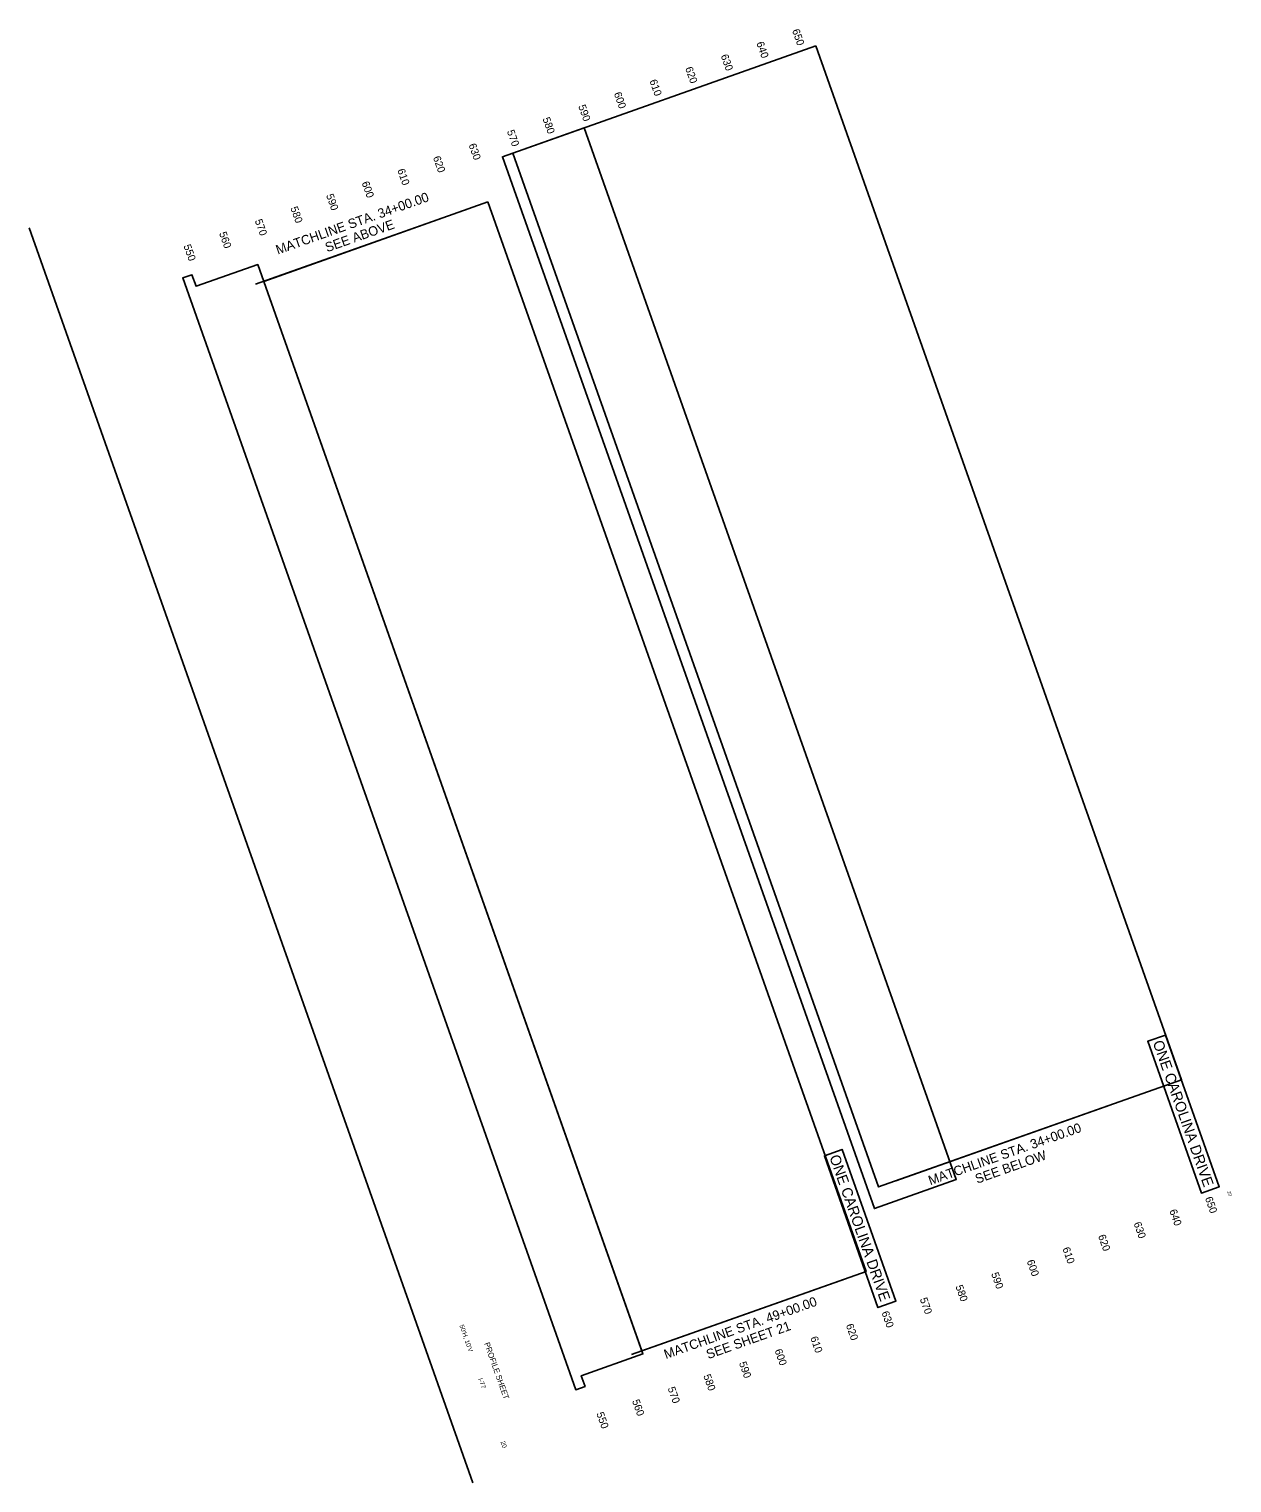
# Model space of a CAD drawing. Extents: x 1995206 to 1996796, y 1127223 to 1129145.
import ezdxf

# ---------------------------------------------------------------- set-up
doc = ezdxf.new("R2010")
doc.units = 0
for name, color, linetype in [('RD_DDB_ElevTX', 7, 'Continuous'), ('RD_SHT_MatchLine', 7, 'Continuous'), ('RD_SHT_ShtClip', 7, 'Continuous'), ('RD_SHT_TX', 7, 'Continuous')]:
    doc.layers.add(name, color=color, linetype=linetype)

msp = doc.modelspace()

# ---------------------------------------------------------------- linework, layer by layer
at = {"layer": 'RD_SHT_MatchLine'}
for p, q in [((1995787.8, 1128907.4), (1995505, 1128807.4)), ((1996634.9, 1127722.1), (1996352.1, 1127622)), ((1996285.2, 1127492.3), (1996002.3, 1127392.2))]:
    msp.add_line(p, q, dxfattribs=at)
at = {"layer": 'RD_SHT_ShtClip'}
for points in [[(1996246.1, 1129122.6), (1996729.6, 1127755.6), (1996329, 1127613.9), (1995845.4, 1128980.8)], [(1995939.8, 1129014.3), (1996431.8, 1127623.7), (1996323.5, 1127585.4), (1995831.6, 1128976)], [(1995812.2, 1128916.1), (1996312.5, 1127502), (1996016.1, 1127397.1), (1995515.8, 1128811.2)], [(1995515.8, 1128811.2), (1996017.5, 1127393.2), (1995935.9, 1127364.3), (1995940.9, 1127350.2), (1995928.6, 1127345.9), (1995408.7, 1128815.7), (1995421, 1128820), (1995426.4, 1128804.6), (1995508, 1128833.4)]]:
    msp.add_lwpolyline(points, close=True, dxfattribs=at)
at = {"layer": 'RD_SHT_TX'}
msp.add_line((1995205.5, 1128881.9), (1995792.5, 1127222.6), dxfattribs=at)
for points in [[(1996756.1, 1127605.9), (1996685.1, 1127806.5), (1996708.7, 1127814.8), (1996779.7, 1127614.2)], [(1996708.7, 1127814.8), (1996779.7, 1127614.2), (1996756.1, 1127605.9), (1996685.1, 1127806.5)], [(1996280.9, 1127663.5), (1996351.9, 1127462.9), (1996328.3, 1127454.5), (1996257.4, 1127655.2)], [(1996328.3, 1127454.5), (1996257.4, 1127655.2), (1996280.9, 1127663.5), (1996351.9, 1127462.9)]]:
    msp.add_lwpolyline(points, close=True, dxfattribs=at)

# ---------------------------------------------------------------- texts
at = {"layer": 'RD_DDB_ElevTX'}
for s, p in [('650', (1996214.5, 1129142.9)), ('640', (1996167.3, 1129126.2)), ('630', (1996120.2, 1129109.5)), ('610', (1996025.9, 1129076.2)), ('620', (1996073.1, 1129092.9)), ('600', (1995978.8, 1129059.5)), ('590', (1995931.7, 1129042.8)), ('580', (1995884.5, 1129026.2)), ('570', (1995837.4, 1129009.5)), ('630', (1995786.7, 1128991.6)), ('620', (1995739.6, 1128974.9)), ('600', (1995645.3, 1128941.5)), ('610', (1995692.4, 1128958.2)), ('590', (1995598.2, 1128924.9)), ('580', (1995551, 1128908.2)), ('570', (1995503.9, 1128891.5)), ('560', (1995456.7, 1128874.8)), ('550', (1995409.6, 1128858.1)), ('650', (1996760.6, 1127599.1)), ('640', (1996713.5, 1127582.5)), ('630', (1996666.3, 1127565.8)), ('620', (1996619.2, 1127549.1)), ('610', (1996572.1, 1127532.4)), ('590', (1996477.8, 1127499.1)), ('600', (1996524.9, 1127515.8)), ('580', (1996430.6, 1127482.4)), ('570', (1996383.5, 1127465.7)), ('630', (1996332.8, 1127447.8)), ('620', (1996285.7, 1127431.1)), ('610', (1996238.6, 1127414.5)), ('600', (1996191.4, 1127397.8)), ('580', (1996097.1, 1127364.4)), ('590', (1996144.3, 1127381.1)), ('570', (1996050, 1127347.8)), ('560', (1996002.9, 1127331.1)), ('550', (1995955.7, 1127314.4))]:
    msp.add_text(s, height=10, rotation=289.482, dxfattribs=at).set_placement(p)
at = {"layer": 'RD_SHT_MatchLine'}
for s, p in [('MATCHLINE STA. 34+00.00', (1995534.5, 1128846.5)), ('SEE ABOVE', (1995599.7, 1128849.6)), ('MATCHLINE STA. 34+00.00', (1996397.5, 1127616.1)), ('SEE BELOW', (1996459.4, 1127618.1)), ('MATCHLINE STA. 49+00.00', (1996047.8, 1127386.3)), ('SEE SHEET 21', (1996103.8, 1127386.2))]:
    msp.add_text(s, height=12.5, rotation=19.482, dxfattribs=at).set_placement(p)
at = {"layer": 'RD_SHT_TX'}
for s, height, p in [('ONE CAROLINA DRIVE', 14, (1996691.5, 1127804.9)), ('ONE CAROLINA DRIVE', 14, (1996263.8, 1127653.6)), ('20', 4.5, (1996790.2, 1127607.7)), ("50'H, 10'V", 6, (1995774.6, 1127430.7)), ('PROFILE SHEET', 7.5, (1995807.3, 1127407)), ('I-77', 6, (1995799.5, 1127360.1)), ('20', 6, (1995829, 1127276.8))]:
    msp.add_text(s, height=height, rotation=289.482, dxfattribs=at).set_placement(p)

doc.saveas('drawing.dxf')
